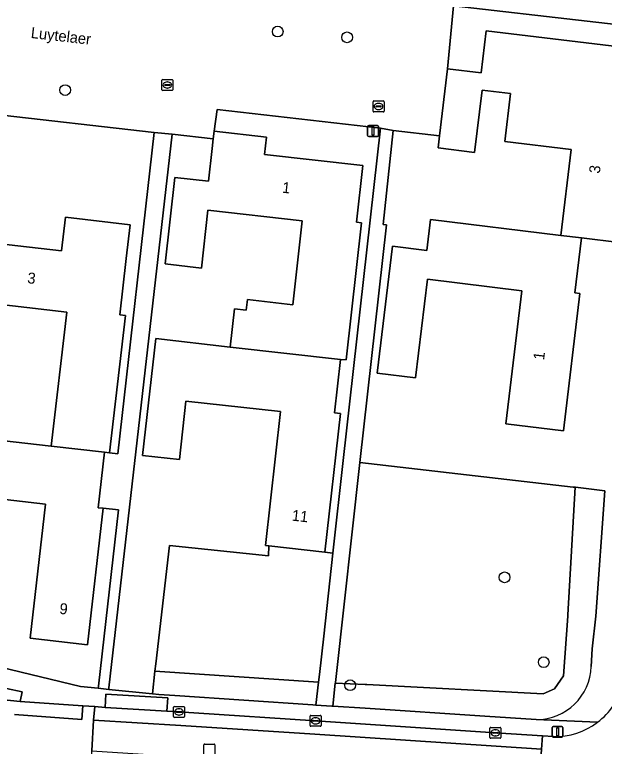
# Model space of a CAD drawing. Extents: x 162396 to 163643, y 386452 to 387406.
# Drawn here: x 162661.5 to 162715.3, y 386600.8 to 386667.5 of the extents above; entities that cross this region are included whole.
import ezdxf

# ---------------------------------------------------------------- set-up
doc = ezdxf.new("R2010")
doc.units = 0
for name, color, linetype in [('IMGEO_Boom', 7, 'Continuous'), ('IMGEO_Erf', 7, 'Continuous'), ('IMGEO_Groenvoorziening', 7, 'Continuous'), ('IMGEO_Kolk', 7, 'Continuous'), ('IMGEO_Lichtmast', 7, 'Continuous'), ('IMGEO_Openbare_ruimte_label', 7, 'Continuous'), ('IMGEO_Pand', 7, 'Continuous'), ('IMGEO_Pand_nummerreeks', 7, 'Continuous'), ('IMGEO_Rijbaan_lokaal_gesloten', 7, 'Continuous'), ('IMGEO_Rijbaan_lokaal_open', 7, 'Continuous'), ('IMGEO_Rioolput', 7, 'Continuous'), ('IMGEO_Voetpad_open', 7, 'Continuous')]:
    doc.layers.add(name, color=color, linetype=linetype)

msp = doc.modelspace()

# ---------------------------------------------------------------- linework, layer by layer
at = {"layer": 'IMGEO_Boom'}
for centre in [(162685.518, 386665.962), (162691.847, 386665.437), (162666.114, 386660.628), (162706.225, 386616.177), (162709.796, 386608.434), (162692.128, 386606.334)]:
    msp.add_circle(centre, 0.489, dxfattribs=at)
at = {"layer": 'IMGEO_Erf'}
for points in [[(162725.964, 386665.516), (162701.576, 386668.308), (162701.024, 386662.577), (162704.091, 386662.206), (162704.554, 386666.036), (162718.242, 386664.379)], [(162716.692, 386646.716), (162713.229, 386647.135), (162712.624, 386642.137), (162713.105, 386642.079), (162711.59, 386629.556), (162706.339, 386630.192), (162707.807, 386642.323), (162699.185, 386643.366), (162698.096, 386634.373), (162694.58, 386634.799), (162695.982, 386646.384), (162699.118, 386646.004), (162699.458, 386648.812), (162711.349, 386647.375), (162712.295, 386655.194), (162706.238, 386655.927), (162706.769, 386660.319), (162704.178, 386660.632), (162703.489, 386654.941), (162700.149, 386655.346), (162700.284, 386656.459), (162696.053, 386656.935), (162695.149, 386648.38), (162695.439, 386648.33), (162693.02, 386626.657), (162712.472, 386624.417), (162712.66, 386624.395), (162712.686, 386624.392), (162715.359, 386624.084)], [(162654.858, 386647.214), (162665.781, 386645.959), (162666.133, 386649.023), (162672.045, 386648.344), (162671.693, 386645.279), (162671.1, 386640.115), (162671.613, 386640.056), (162670.175, 386627.541), (162670.931, 386627.451), (162674.242, 386656.758), (162659.28, 386658.465)], [(162652.822, 386629.527), (162664.854, 386628.145), (162666.259, 386640.378), (162657.629, 386641.37)], [(162660.214, 386607.974), (162667.525, 386606.224), (162669.127, 386606.059), (162669.149, 386606.263), (162670.988, 386622.332), (162669.594, 386622.475), (162668.163, 386610.017), (162662.914, 386610.62), (162664.319, 386622.854), (162655.606, 386623.855)]]:
    msp.add_lwpolyline(points, dxfattribs=at)
for points in [[(162691.504, 386626.852), (162694.884, 386657.146), (162679.981, 386658.864), (162679.727, 386656.879), (162684.501, 386656.341), (162684.322, 386654.747), (162693.293, 386653.737), (162692.712, 386648.582), (162693.167, 386648.531), (162691.758, 386636.008), (162691.26, 386636.064), (162690.712, 386631.191), (162691.232, 386631.132), (162689.808, 386618.479), (162690.56, 386618.394)], [(162685.771, 386631.292), (162677.145, 386632.263), (162676.543, 386626.919), (162673.19, 386627.297), (162674.39, 386637.951), (162681.169, 386637.188), (162681.561, 386640.666), (162682.646, 386640.544), (162682.756, 386641.515), (162686.897, 386641.049), (162687.757, 386648.694), (162679.141, 386649.663), (162678.548, 386644.393), (162675.233, 386644.766), (162676.122, 386652.665), (162679.187, 386652.32), (162679.521, 386655.287), (162679.639, 386656.195), (162675.871, 386656.617), (162670.104, 386606.108), (162670.089, 386605.959), (162674.077, 386605.548), (162674.315, 386607.614), (162674.394, 386608.301), (162675.637, 386619.094), (162684.681, 386618.151), (162684.719, 386619.052), (162684.397, 386619.088)]]:
    msp.add_lwpolyline(points, close=True, dxfattribs=at)
at = {"layer": 'IMGEO_Groenvoorziening'}
for points in [[(162712.66, 386624.395), (162712.472, 386624.417), (162693.02, 386626.657), (162690.839, 386607.119), (162690.779, 386606.582), (162690.772, 386606.523), (162693.507, 386606.409), (162693.65, 386606.401), (162709.758, 386605.544), (162710.781, 386606.022), (162711.6, 386607.182), (162711.998, 386612.625), (162712.009, 386612.773)], [(162690.56, 386618.394), (162689.808, 386618.479), (162684.719, 386619.052), (162684.681, 386618.151), (162675.637, 386619.094), (162674.394, 386608.301), (162674.315, 386607.614), (162689.244, 386606.609), (162689.324, 386607.324), (162689.715, 386610.823)], [(162689.244, 386606.609), (162674.315, 386607.614), (162674.077, 386605.548), (162674.658, 386605.488), (162676.123, 386605.389), (162688.73, 386604.537), (162689.011, 386604.52)]]:
    msp.add_lwpolyline(points, close=True, dxfattribs=at)
for points in [[(162715.359, 386624.084), (162712.686, 386624.392), (162712.66, 386624.395), (162712.009, 386612.773), (162711.998, 386612.625), (162711.6, 386607.182), (162710.781, 386606.022), (162709.758, 386605.544), (162693.65, 386606.401), (162693.507, 386606.409), (162690.772, 386606.523), (162690.538, 386604.425), (162693.485, 386604.233), (162704.425, 386603.521), (162706.774, 386603.352), (162709.121, 386603.197)], [(162714.124, 386608.058), (162714.22, 386609.663), (162714.566, 386612.643), (162715.359, 386624.084)], [(162658.459, 386605.21), (162662.021, 386604.865), (162662.181, 386605.746), (162660.775, 386606.047)]]:
    msp.add_lwpolyline(points, dxfattribs=at)
msp.add_arc((162709.132, 386608.191), 4.994, 269.87697, 358.47351, dxfattribs=at)
at = {"layer": 'IMGEO_Kolk'}
for p, q in [((162674.946, 386660.665), (162674.946, 386661.517)), ((162675.021, 386661.591), (162675.873, 386661.591)), ((162675.434, 386661.371), (162675.459, 386661.371)), ((162675.947, 386661.517), (162675.947, 386660.665)), ((162675.205, 386661.085), (162675.205, 386661.097)), ((162675.643, 386661.048), (162675.245, 386661.048)), ((162675.248, 386661.134), (162675.646, 386661.134)), ((162675.457, 386660.811), (162675.432, 386660.811)), ((162675.689, 386661.097), (162675.689, 386661.085)), ((162675.873, 386660.591), (162675.021, 386660.591)), ((162694.217, 386658.709), (162694.217, 386659.561)), ((162694.292, 386659.635), (162695.144, 386659.635)), ((162694.705, 386659.415), (162694.73, 386659.415)), ((162695.218, 386659.561), (162695.218, 386658.709)), ((162695.144, 386658.635), (162694.292, 386658.635)), ((162694.476, 386659.129), (162694.476, 386659.141)), ((162694.914, 386659.092), (162694.516, 386659.092)), ((162694.519, 386659.178), (162694.917, 386659.178)), ((162694.728, 386658.855), (162694.703, 386658.855)), ((162694.96, 386659.141), (162694.96, 386659.129)), ((162676.012, 386603.473), (162676.012, 386604.325)), ((162676.087, 386604.399), (162676.939, 386604.399)), ((162676.271, 386603.893), (162676.271, 386603.905)), ((162676.314, 386603.942), (162676.712, 386603.942)), ((162676.5, 386604.179), (162676.525, 386604.179)), ((162676.755, 386603.905), (162676.755, 386603.893)), ((162677.013, 386604.325), (162677.013, 386603.473)), ((162676.939, 386603.399), (162676.087, 386603.399)), ((162676.709, 386603.856), (162676.311, 386603.856)), ((162676.523, 386603.619), (162676.498, 386603.619)), ((162688.468, 386602.663), (162688.468, 386603.515)), ((162688.543, 386603.589), (162689.395, 386603.589)), ((162688.956, 386603.369), (162688.981, 386603.369)), ((162689.469, 386603.515), (162689.469, 386602.663)), ((162689.395, 386602.589), (162688.543, 386602.589)), ((162688.727, 386603.083), (162688.727, 386603.095)), ((162689.165, 386603.046), (162688.767, 386603.046)), ((162688.77, 386603.132), (162689.168, 386603.132)), ((162688.979, 386602.809), (162688.954, 386602.809)), ((162689.211, 386603.095), (162689.211, 386603.083)), ((162704.884, 386601.569), (162704.884, 386602.421)), ((162704.959, 386602.495), (162705.811, 386602.495)), ((162705.143, 386601.989), (162705.143, 386602.001)), ((162705.581, 386601.952), (162705.183, 386601.952)), ((162705.186, 386602.038), (162705.584, 386602.038)), ((162705.372, 386602.275), (162705.397, 386602.275)), ((162705.627, 386602.001), (162705.627, 386601.989)), ((162705.885, 386602.421), (162705.885, 386601.569)), ((162705.811, 386601.495), (162704.959, 386601.495)), ((162705.395, 386601.715), (162705.37, 386601.715))]:
    msp.add_line(p, q, dxfattribs=at)
for points in [[(162674.946, 386660.665), (162674.946, 386661.517)], [(162675.021, 386661.591), (162675.873, 386661.591)], [(162675.947, 386661.517), (162675.947, 386660.665)], [(162675.873, 386660.591), (162675.021, 386660.591)], [(162694.217, 386658.709), (162694.217, 386659.561)], [(162694.292, 386659.635), (162695.144, 386659.635)], [(162695.218, 386659.561), (162695.218, 386658.709)], [(162695.144, 386658.635), (162694.292, 386658.635)], [(162676.012, 386603.473), (162676.012, 386604.325)], [(162676.087, 386604.399), (162676.939, 386604.399)], [(162677.013, 386604.325), (162677.013, 386603.473)], [(162676.939, 386603.399), (162676.087, 386603.399)], [(162688.468, 386602.663), (162688.468, 386603.515)], [(162688.543, 386603.589), (162689.395, 386603.589)], [(162689.469, 386603.515), (162689.469, 386602.663)], [(162689.395, 386602.589), (162688.543, 386602.589)], [(162704.884, 386601.569), (162704.884, 386602.421)], [(162704.959, 386602.495), (162705.811, 386602.495)], [(162705.885, 386602.421), (162705.885, 386601.569)], [(162705.811, 386601.495), (162704.959, 386601.495)]]:
    msp.add_lwpolyline(points, dxfattribs=at)
for centre, radius, start, end in [((162675.023, 386661.515), 0.0765, 91.55205, 178.44795), ((162675.023, 386661.515), 0.0765, 91.55205, 178.44795), ((162675.871, 386661.515), 0.0765, 1.55205, 88.44795), ((162675.871, 386661.515), 0.0765, 1.55205, 88.44795), ((162675.023, 386660.667), 0.0765, 181.55205, 268.44795), ((162675.023, 386660.667), 0.0765, 181.55205, 268.44795), ((162675.245, 386661.094), 0.0403, 85.87752, 175.75265), ((162675.242, 386661.084), 0.0366, 178.93798, 274.71019), ((162675.646, 386661.091), 0.043, 264.86636, 352.45326), ((162675.65, 386661.096), 0.0386, 1.73085, 96.63898), ((162675.871, 386660.667), 0.0765, 271.55205, 358.44795), ((162675.871, 386660.667), 0.0765, 271.55205, 358.44795), ((162694.294, 386659.559), 0.0765, 91.55205, 178.44795), ((162694.294, 386659.559), 0.0765, 91.55205, 178.44795), ((162695.142, 386659.559), 0.0765, 1.55205, 88.44795), ((162695.142, 386659.559), 0.0765, 1.55205, 88.44795), ((162694.294, 386658.711), 0.0765, 181.55205, 268.44795), ((162694.294, 386658.711), 0.0765, 181.55205, 268.44795), ((162694.516, 386659.138), 0.0403, 85.87752, 175.75265), ((162694.513, 386659.128), 0.0366, 178.93798, 274.71019), ((162694.917, 386659.135), 0.043, 264.86636, 352.45326), ((162694.921, 386659.14), 0.0386, 1.73085, 96.63898), ((162695.142, 386658.711), 0.0765, 271.55205, 358.44795), ((162695.142, 386658.711), 0.0765, 271.55205, 358.44795), ((162676.089, 386604.323), 0.0765, 91.55205, 178.44795), ((162676.089, 386604.323), 0.0765, 91.55205, 178.44795), ((162676.311, 386603.902), 0.0403, 85.87752, 175.75265), ((162676.716, 386603.904), 0.0386, 1.73085, 96.63898), ((162676.937, 386604.323), 0.0765, 1.55205, 88.44795), ((162676.937, 386604.323), 0.0765, 1.55205, 88.44795), ((162676.089, 386603.475), 0.0765, 181.55205, 268.44795), ((162676.089, 386603.475), 0.0765, 181.55205, 268.44795), ((162676.308, 386603.892), 0.0366, 178.93798, 274.71019), ((162676.712, 386603.899), 0.043, 264.86636, 352.45326), ((162676.937, 386603.475), 0.0765, 271.55205, 358.44795), ((162676.937, 386603.475), 0.0765, 271.55205, 358.44795), ((162688.545, 386603.513), 0.0765, 91.55205, 178.44795), ((162688.545, 386603.513), 0.0765, 91.55205, 178.44795), ((162689.393, 386603.513), 0.0765, 1.55205, 88.44795), ((162689.393, 386603.513), 0.0765, 1.55205, 88.44795), ((162688.545, 386602.665), 0.0765, 181.55205, 268.44795), ((162688.545, 386602.665), 0.0765, 181.55205, 268.44795), ((162688.767, 386603.092), 0.0403, 85.87752, 175.75265), ((162688.764, 386603.082), 0.0366, 178.93798, 274.71019), ((162689.168, 386603.089), 0.043, 264.86636, 352.45326), ((162689.172, 386603.094), 0.0386, 1.73085, 96.63898), ((162689.393, 386602.665), 0.0765, 271.55205, 358.44795), ((162689.393, 386602.665), 0.0765, 271.55205, 358.44795), ((162704.961, 386602.419), 0.0765, 91.55205, 178.44795), ((162704.961, 386602.419), 0.0765, 91.55205, 178.44795), ((162705.183, 386601.998), 0.0403, 85.87752, 175.75265), ((162705.18, 386601.988), 0.0366, 178.93798, 274.71019), ((162705.584, 386601.995), 0.043, 264.86636, 352.45326), ((162705.588, 386602), 0.0386, 1.73085, 96.63898), ((162705.809, 386602.419), 0.0765, 1.55205, 88.44795), ((162705.809, 386602.419), 0.0765, 1.55205, 88.44795), ((162704.961, 386601.571), 0.0765, 181.55205, 268.44795), ((162704.961, 386601.571), 0.0765, 181.55205, 268.44795), ((162705.809, 386601.571), 0.0765, 271.55205, 358.44795), ((162705.809, 386601.571), 0.0765, 271.55205, 358.44795)]:
    msp.add_arc(centre, radius, start, end, dxfattribs=at)
for centre, major_axis, ratio, start_param, end_param in [((162675.433, 386661.091), (-0.387, 0.002), 0.722429, 4.712389, 7.853982), ((162675.458, 386661.091), (-0.39, 0.002), 0.717154, 1.570796, 4.712389), ((162694.704, 386659.135), (-0.387, 0.002), 0.722429, 4.712389, 7.853982), ((162694.729, 386659.135), (-0.39, 0.002), 0.717154, 1.570796, 4.712389), ((162676.499, 386603.899), (-0.387, 0.002), 0.722429, 4.712389, 7.853982), ((162676.524, 386603.899), (-0.39, 0.002), 0.717154, 1.570796, 4.712389), ((162688.955, 386603.089), (-0.387, 0.002), 0.722429, 4.712389, 7.853982), ((162688.98, 386603.089), (-0.39, 0.002), 0.717154, 1.570796, 4.712389), ((162705.371, 386601.995), (-0.387, 0.002), 0.722429, 4.712389, 7.853982), ((162705.396, 386601.995), (-0.39, 0.002), 0.717154, 1.570796, 4.712389)]:
    msp.add_ellipse(centre, major_axis=major_axis, ratio=ratio, start_param=start_param, end_param=end_param, dxfattribs=at)
at = {"layer": 'IMGEO_Lichtmast'}
for p, q in [((162693.824, 386657.399), (162694.614, 386657.399)), ((162694.614, 386657.399), (162693.824, 386657.399)), ((162693.724, 386656.499), (162693.724, 386657.299)), ((162693.724, 386657.299), (162693.724, 386656.499)), ((162694.714, 386657.299), (162694.714, 386656.499)), ((162694.714, 386656.499), (162694.714, 386657.299)), ((162694.614, 386656.399), (162693.824, 386656.399)), ((162693.824, 386656.399), (162694.614, 386656.399)), ((162710.664, 386602.585), (162711.454, 386602.585)), ((162711.454, 386602.585), (162710.664, 386602.585)), ((162710.564, 386601.685), (162710.564, 386602.485)), ((162710.564, 386602.485), (162710.564, 386601.685)), ((162711.554, 386602.485), (162711.554, 386601.685)), ((162711.554, 386601.685), (162711.554, 386602.485)), ((162711.454, 386601.585), (162710.664, 386601.585)), ((162710.664, 386601.585), (162711.454, 386601.585))]:
    msp.add_line(p, q, dxfattribs=at)
for points in [[(162694.144, 386657.274), (162694.294, 386657.274), (162694.294, 386656.524), (162694.144, 386656.524), (162694.144, 386657.274)], [(162710.984, 386602.46), (162711.134, 386602.46), (162711.134, 386601.71), (162710.984, 386601.71), (162710.984, 386602.46)]]:
    msp.add_lwpolyline(points, dxfattribs=at)
for centre, start, end in [((162693.824, 386657.299), 90, 180), ((162693.824, 386657.299), 90, 180), ((162694.614, 386657.299), 0, 90), ((162694.614, 386657.299), 360, 90), ((162693.824, 386656.499), 180, 270), ((162693.824, 386656.499), 180, 270), ((162694.614, 386656.499), 270, 0), ((162694.614, 386656.499), 270, 0), ((162710.664, 386602.485), 90, 180), ((162710.664, 386602.485), 90, 180), ((162711.454, 386602.485), 0, 90), ((162711.454, 386602.485), 360, 90), ((162710.664, 386601.685), 180, 270), ((162710.664, 386601.685), 180, 270), ((162711.454, 386601.685), 270, 0), ((162711.454, 386601.685), 270, 0)]:
    msp.add_arc(centre, 0.1, start, end, dxfattribs=at)
at = {"layer": 'IMGEO_Pand'}
for points in [[(162700.284, 386656.459), (162700.149, 386655.346), (162703.489, 386654.941), (162704.178, 386660.632), (162706.769, 386660.319), (162706.238, 386655.927), (162712.295, 386655.194), (162711.349, 386647.375), (162713.229, 386647.135), (162716.692, 386646.716), (162718.2, 386659.172), (162717.621, 386659.242), (162718.242, 386664.379), (162704.554, 386666.036), (162704.091, 386662.206), (162701.024, 386662.577)], [(162679.639, 386656.195), (162679.521, 386655.287), (162679.187, 386652.32), (162676.122, 386652.665), (162675.233, 386644.766), (162678.548, 386644.393), (162679.141, 386649.663), (162687.757, 386648.694), (162686.897, 386641.049), (162682.756, 386641.515), (162682.646, 386640.544), (162681.561, 386640.666), (162681.169, 386637.188), (162691.26, 386636.064), (162691.758, 386636.008), (162693.167, 386648.531), (162692.712, 386648.582), (162693.293, 386653.737), (162684.322, 386654.747), (162684.501, 386656.341), (162679.727, 386656.879)], [(162670.175, 386627.541), (162671.613, 386640.056), (162671.1, 386640.115), (162671.693, 386645.279), (162672.045, 386648.344), (162666.133, 386649.023), (162665.781, 386645.959), (162654.858, 386647.214), (162653.615, 386636.397), (162657.013, 386636.007), (162657.629, 386641.37), (162666.259, 386640.378), (162664.854, 386628.145), (162669.702, 386627.595)], [(162711.349, 386647.375), (162699.458, 386648.812), (162699.118, 386646.004), (162695.982, 386646.384), (162694.58, 386634.799), (162698.096, 386634.373), (162699.185, 386643.366), (162707.807, 386642.323), (162706.339, 386630.192), (162711.59, 386629.556), (162713.105, 386642.079), (162712.624, 386642.137), (162713.229, 386647.135)], [(162689.808, 386618.479), (162691.232, 386631.132), (162690.712, 386631.191), (162691.26, 386636.064), (162681.169, 386637.188), (162674.39, 386637.951), (162673.19, 386627.297), (162676.543, 386626.919), (162677.145, 386632.263), (162685.771, 386631.292), (162684.397, 386619.088), (162684.719, 386619.052)], [(162669.12, 386622.53), (162669.702, 386627.595), (162664.854, 386628.145), (162652.822, 386629.527), (162651.596, 386618.855), (162654.986, 386618.465), (162655.606, 386623.855), (162664.319, 386622.854), (162662.914, 386610.62), (162668.163, 386610.017), (162669.594, 386622.475)]]:
    msp.add_lwpolyline(points, close=True, dxfattribs=at)
at = {"layer": 'IMGEO_Rijbaan_lokaal_gesloten'}
msp.add_lwpolyline([(162661.504, 386603.662), (162667.645, 386603.213), (162667.733, 386604.463), (162662.021, 386604.865), (162658.459, 386605.21)], dxfattribs=at)
msp.add_lwpolyline([(162688.969, 386603.089), (162677.862, 386603.812), (162676.513, 386603.899), (162675.41, 386603.974), (162669.759, 386604.318), (162668.821, 386604.393), (162668.709, 386603.157), (162676.668, 386602.653), (162688.895, 386601.878), (162709.59, 386600.492), (162709.68, 386601.72), (162705.385, 386601.995)], close=True, dxfattribs=at)
at = {"layer": 'IMGEO_Rijbaan_lokaal_open'}
for points in [[(162610.449, 386668.978), (162609.92, 386663.966), (162614.719, 386663.466), (162633.536, 386661.425), (162633.187, 386658.247), (162628.73, 386617.707), (162630.221, 386617.233), (162634.64, 386658.079), (162653.657, 386655.937), (162654.99, 386655.608), (162658.928, 386655.156), (162659.28, 386658.465), (162674.242, 386656.758), (162675.871, 386656.617), (162679.639, 386656.195), (162679.727, 386656.879), (162679.981, 386658.864), (162694.884, 386657.146), (162696.053, 386656.935), (162700.284, 386656.459), (162701.024, 386662.577), (162701.576, 386668.308), (162725.964, 386665.516)], [(162668.709, 386603.157), (162668.821, 386604.393), (162667.733, 386604.463), (162667.645, 386603.213), (162661.504, 386603.662)], [(162667.457, 386599.084), (162668.485, 386599.078), (162668.549, 386600.361), (162668.709, 386603.157)], [(162710.691, 386601.655), (162709.68, 386601.72), (162709.59, 386600.492), (162709.416, 386597.686), (162709.355, 386596.471), (162710.397, 386596.361), (162710.468, 386597.592), (162728.355, 386596.42), (162728.298, 386595.17), (162729.341, 386595.142), (162729.422, 386596.356), (162729.614, 386599.202), (162729.676, 386600.429), (162728.827, 386600.5), (162728.672, 386600.508)]]:
    msp.add_lwpolyline(points, dxfattribs=at)
msp.add_lwpolyline([(162709.59, 386600.492), (162688.895, 386601.878), (162676.668, 386602.653), (162668.709, 386603.157), (162668.549, 386600.361), (162688.279, 386599.062), (162709.416, 386597.686)], close=True, dxfattribs=at)
for centre, radius, start, end in [((162710.819, 386608.108), 6.455, 307.03446, 344.1867), ((162710.818, 386608.116), 6.463, 268.8756, 306.99847)]:
    msp.add_arc(centre, radius, start, end, dxfattribs=at)
at = {"layer": 'IMGEO_Rioolput'}
for p, q in [((162678.781, 386600.042), (162678.781, 386600.894)), ((162678.856, 386600.968), (162679.708, 386600.968)), ((162679.782, 386600.894), (162679.782, 386600.042))]:
    msp.add_line(p, q, dxfattribs=at)
for points in [[(162678.781, 386600.042), (162678.781, 386600.894)], [(162678.856, 386600.968), (162679.708, 386600.968)], [(162679.782, 386600.894), (162679.782, 386600.042)]]:
    msp.add_lwpolyline(points, dxfattribs=at)
for centre, start, end in [((162678.858, 386600.892), 91.55205, 178.44795), ((162678.858, 386600.892), 91.55205, 178.44795), ((162679.706, 386600.892), 1.55205, 88.44795), ((162679.706, 386600.892), 1.55205, 88.44795)]:
    msp.add_arc(centre, 0.0765, start, end, dxfattribs=at)
at = {"layer": 'IMGEO_Voetpad_open'}
for points in [[(162675.871, 386656.617), (162674.242, 386656.758), (162670.931, 386627.451), (162670.175, 386627.541), (162669.702, 386627.595), (162669.12, 386622.53), (162669.594, 386622.475), (162670.988, 386622.332), (162669.149, 386606.263), (162669.127, 386606.059), (162670.089, 386605.959), (162670.104, 386606.108)], [(162695.439, 386648.33), (162695.149, 386648.38), (162696.053, 386656.935), (162694.884, 386657.146), (162691.504, 386626.852), (162690.56, 386618.394), (162689.715, 386610.823), (162689.324, 386607.324), (162689.244, 386606.609), (162689.011, 386604.52), (162690.469, 386604.43), (162690.538, 386604.425), (162690.772, 386606.523), (162690.779, 386606.582), (162690.839, 386607.119), (162693.02, 386626.657)], [(162669.759, 386604.318), (162675.41, 386603.974), (162675.484, 386605.175), (162669.834, 386605.531)]]:
    msp.add_lwpolyline(points, close=True, dxfattribs=at)
for points in [[(162715.359, 386624.084), (162714.566, 386612.643), (162714.22, 386609.663), (162714.124, 386608.058)], [(162714.707, 386602.955), (162709.121, 386603.197), (162706.774, 386603.352), (162704.425, 386603.521), (162693.485, 386604.233), (162690.538, 386604.425), (162690.469, 386604.43), (162689.011, 386604.52), (162688.73, 386604.537), (162676.123, 386605.389), (162674.658, 386605.488), (162674.077, 386605.548), (162670.089, 386605.959), (162669.127, 386606.059), (162667.525, 386606.224), (162660.214, 386607.974)], [(162660.775, 386606.047), (162662.181, 386605.746), (162662.021, 386604.865), (162667.733, 386604.463), (162668.821, 386604.393), (162669.759, 386604.318), (162669.834, 386605.531), (162675.484, 386605.175), (162675.41, 386603.974), (162676.513, 386603.899), (162677.862, 386603.812), (162688.969, 386603.089), (162705.385, 386601.995), (162709.68, 386601.72), (162710.691, 386601.655)], [(162709.121, 386603.197), (162714.707, 386602.955)]]:
    msp.add_lwpolyline(points, dxfattribs=at)
for centre, radius, start, end in [((162709.132, 386608.191), 4.994, 269.87697, 358.47351), ((162710.819, 386608.108), 6.455, 307.03446, 344.1867), ((162710.818, 386608.116), 6.463, 268.8756, 306.99847)]:
    msp.add_arc(centre, radius, start, end, dxfattribs=at)

# ---------------------------------------------------------------- texts
at = {"layer": 'IMGEO_Openbare_ruimte_label'}
msp.add_text('Luytelaer', height=1, rotation=353.51434, dxfattribs=at).set_placement((162662.947, 386665.385))
at = {"layer": 'IMGEO_Pand_nummerreeks'}
for s, rotation, p in [('3', 83.09701, (162714.911, 386652.974)), ('1', 353.57854, (162685.88, 386651.27)), ('3', 353.44325, (162662.627, 386643.019)), ('1', 83.10203, (162709.826, 386635.961)), ('11', 353.57847, (162686.767, 386621.357)), ('9', 353.44664, (162665.552, 386612.854))]:
    msp.add_text(s, height=1, rotation=rotation, dxfattribs=at).set_placement(p)

doc.saveas('drawing.dxf')
